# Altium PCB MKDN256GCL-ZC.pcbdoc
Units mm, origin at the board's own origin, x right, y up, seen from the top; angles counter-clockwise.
Board outline 26.52 x 21.76 mm, 2 copper layers (Top Layer, Bottom Layer), stack 0 mm thick; 1 components, 0 nets, 20 pads, 0 vias.
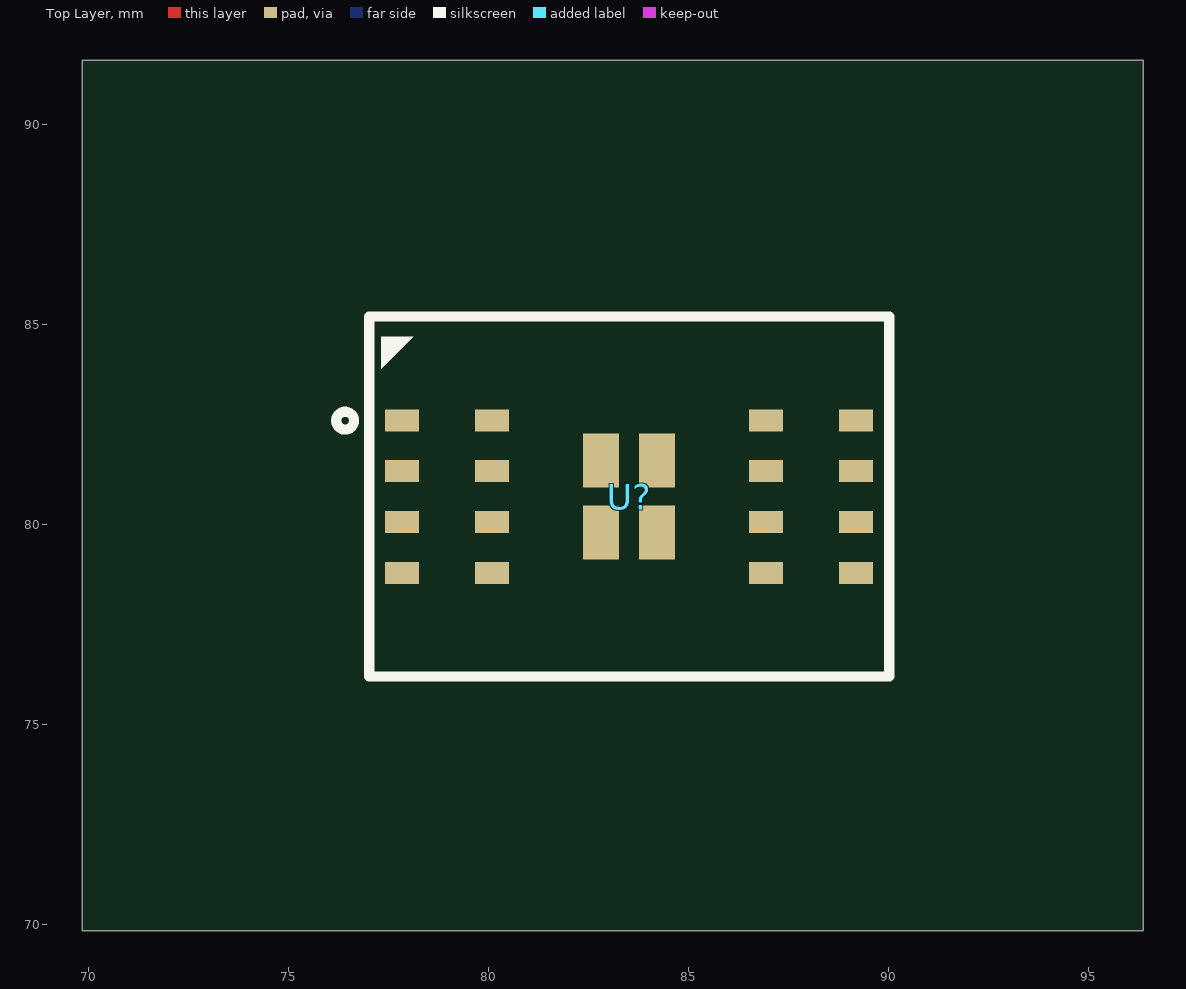
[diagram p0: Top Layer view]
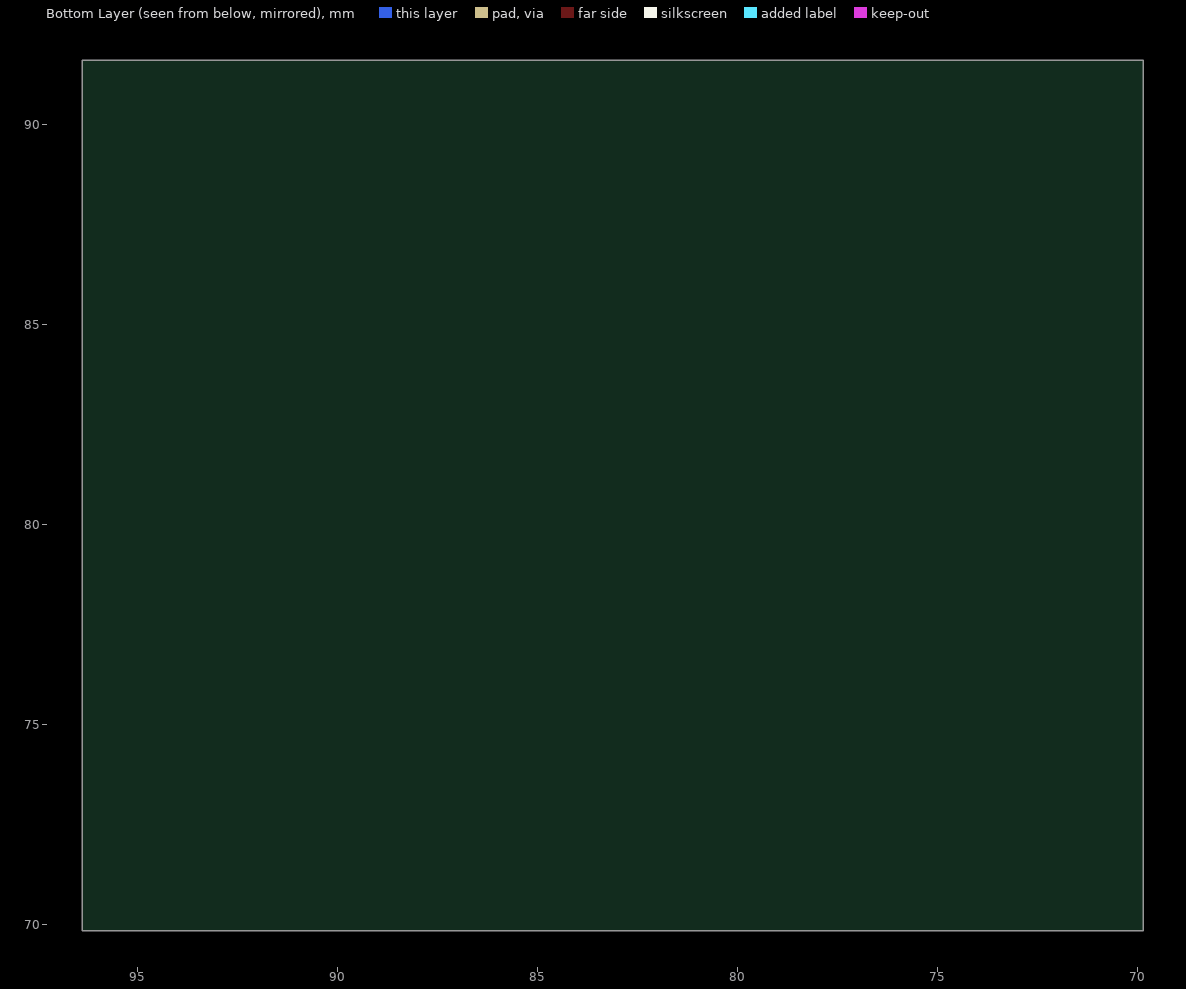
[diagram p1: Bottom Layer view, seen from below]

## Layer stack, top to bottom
Top Layer: signal copper (thickness not stored)
Bottom Layer: signal copper (thickness not stored)

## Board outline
96.374,69.85 69.85,69.85 69.85,91.61 96.374,91.61

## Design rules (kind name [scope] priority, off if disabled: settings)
PasteMaskExpansion "Paste Mask Expansion" [All] p1: expansion=0
SolderMaskExpansion "Solder Mask Expansion" [IsVia] p1: expansion=-25.4 istentingtop=TRUE
SolderMaskExpansion "Solder Mask Expansion" [All] p2: expansion=0.051 istentingtop=FALSE

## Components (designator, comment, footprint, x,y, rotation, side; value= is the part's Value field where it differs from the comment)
U? "MKDN256GCL-ZC" LGA-16_L13.0-W9.0-P1.27-TL 83.524,80.7 r0 top

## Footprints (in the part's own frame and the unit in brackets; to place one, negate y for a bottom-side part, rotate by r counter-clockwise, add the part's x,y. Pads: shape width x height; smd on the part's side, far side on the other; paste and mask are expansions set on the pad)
LGA-16_L13.0-W9.0-P1.27-TL [mm]
  rect 0.85x0.55 smd: 1(-5.675,1.905) 1(-3.425,1.905) 2(-5.675,0.635) 2(-3.425,0.635) 3(-5.675,-0.635) 3(-3.425,-0.635) 4(-5.675,-1.905) 4(-3.425,-1.905) 5(3.425,-1.905) 5(5.675,-1.905) 6(3.425,-0.635) 6(5.675,-0.635) 7(3.425,0.635) 7(5.675,0.635) 8(3.425,1.905) 8(5.675,1.905)
  rect 0.9x1.35 smd: 9(-0.7,0.9) 10(-0.7,-0.9) 11(0.7,-0.9) 12(0.7,0.9)
  silkscreen extent -7.32,-4.5 6.5,4.5

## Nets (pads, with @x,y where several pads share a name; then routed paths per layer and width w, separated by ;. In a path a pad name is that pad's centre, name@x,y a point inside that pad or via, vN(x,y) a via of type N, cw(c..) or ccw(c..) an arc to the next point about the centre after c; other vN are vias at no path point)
pads on no net: U?.1 U?.2 U?.3 U?.4 U?.5 U?.6 U?.7 U?.8 U?.9 U?.10 U?.11 U?.12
